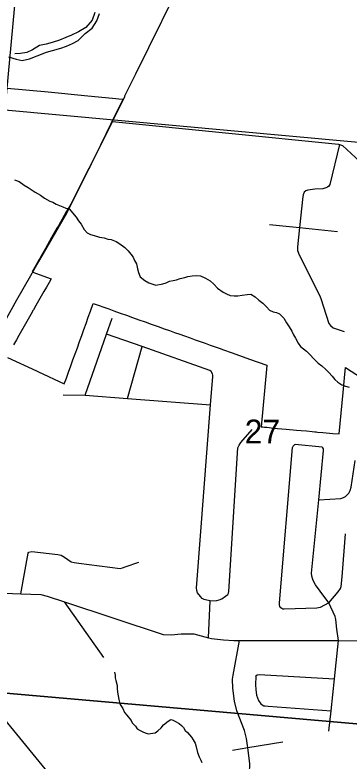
# Model space of a CAD drawing. Extents: x 0 to 34, y -3.9 to 26.2.
# Drawn here: x 4.192 to 4.778, y 19.139 to 20.448 of the extents above; entities that cross this region are included whole.
import ezdxf

# ---------------------------------------------------------------- set-up
doc = ezdxf.new("R2010")
doc.units = 0
for name, color, linetype in [('GM_X_City_Street', 7, 'Continuous'), ('GM_X_Corporation', 7, 'Continuous'), ('GM_X_County_Road', 7, 'Continuous'), ('GM_X_Interchange_Ramps', 7, 'Continuous'), ('GM_X_Minor_River', 7, 'Continuous'), ('GM_X_Section', 7, 'Continuous'), ('GM_X_Section_Text', 7, 'Continuous'), ('GM_X_State_Shield', 7, 'Continuous'), ('GM_X_US_Route', 7, 'Continuous')]:
    doc.layers.add(name, color=color, linetype=linetype)

msp = doc.modelspace()

# ---------------------------------------------------------------- linework, layer by layer
at = {"layer": 'GM_X_City_Street'}
for p, q in [((4.3893, 19.7752), (4.4152, 19.8662)), ((4.3477, 19.3208), (4.2785, 19.4187)), ((4.5311, 19.3555), (4.5342, 19.4203))]:
    msp.add_line(p, q, dxfattribs=at)
for points in [[(4.7613, 20.2207), (4.7441, 20.1505), (4.7422, 20.1479), (4.7398, 20.1461), (4.7371, 20.1448), (4.7318, 20.1432), (4.7177, 20.1423), (4.7056, 20.1406), (4.7019, 20.1392), (4.6994, 20.1369), (4.6976, 20.1327), (4.6966, 20.1294), (4.691, 20.075), (4.6875, 20.0413), (4.6873, 20.0367), (4.6877, 20.0345), (4.6906, 20.0272), (4.7262, 19.9566), (4.7283, 19.9506), (4.7424, 19.9068), (4.7453, 19.903), (4.7502, 19.8991), (4.7695, 19.8926)], [(4.6384, 20.0803), (4.691, 20.075), (4.7578, 20.0681)], [(4.3151, 19.7808), (4.3525, 19.8883), (4.3622, 19.9162)], [(4.5342, 19.4203), (4.5282, 19.4213), (4.524, 19.4224), (4.5204, 19.4245), (4.517, 19.4279), (4.5122, 19.4341), (4.5108, 19.4382), (4.5105, 19.4429), (4.5113, 19.4577), (4.5351, 19.7643), (4.539, 19.8139), (4.5387, 19.8161), (4.5382, 19.8183), (4.536, 19.8224), (4.5338, 19.8244), (4.4152, 19.8662), (4.3525, 19.8883)], [(4.2765, 19.7814), (4.3151, 19.7808), (4.3893, 19.7752), (4.5351, 19.7643)], [(4.5342, 19.4203), (4.546, 19.4207), (4.55, 19.4219), (4.5548, 19.4239), (4.5613, 19.4283), (4.565, 19.4315), (4.5663, 19.4337), (4.5671, 19.4369), (4.5828, 19.6886), (4.5852, 19.6934), (4.5883, 19.6979), (4.6079, 19.7209)], [(4.7421, 19.4167), (4.7273, 19.4087), (4.7212, 19.4073), (4.6643, 19.4054), (4.6615, 19.4057), (4.6581, 19.408), (4.6564, 19.4102), (4.6559, 19.413), (4.6558, 19.4166), (4.6788, 19.689), (4.6791, 19.6901), (4.68, 19.6913)], [(4.7422, 19.1914), (4.7462, 19.2273), (4.7523, 19.2835), (4.7596, 19.3504), (4.7567, 19.3706), (4.7547, 19.3874), (4.7542, 19.3905), (4.7535, 19.3928), (4.7421, 19.4167), (4.7273, 19.4371), (4.7189, 19.4484), (4.7164, 19.4525), (4.7142, 19.4576), (4.7127, 19.4633), (4.7122, 19.469), (4.7246, 19.5975), (4.7329, 19.6838), (4.733, 19.6856), (4.7328, 19.6871), (4.7321, 19.6888), (4.7307, 19.6899), (4.6831, 19.6942), (4.6822, 19.694), (4.6813, 19.6931), (4.68, 19.6913)], [(4.7246, 19.5975), (4.7637, 19.5998), (4.7679, 19.6014), (4.7714, 19.6034), (4.7772, 19.6093), (4.78, 19.6137), (4.7817, 19.6194), (4.7886, 19.6667)], [(4.7421, 19.4167), (4.7588, 19.4363), (4.7628, 19.4419), (4.7643, 19.4456), (4.7659, 19.4623), (4.7716, 19.5377)], [(4.2023, 19.4327), (4.2151, 19.5036), (4.2163, 19.5058), (4.2213, 19.5065), (4.267, 19.5018), (4.2731, 19.5005), (4.2787, 19.497), (4.2906, 19.4887), (4.2955, 19.4874), (4.3038, 19.4864), (4.3764, 19.4769), (4.3806, 19.4783), (4.3852, 19.4801), (4.4089, 19.4882)], [(4.0164, 19.3649), (4.0916, 19.4215), (4.1051, 19.4272), (4.1238, 19.4316), (4.1572, 19.4341), (4.2023, 19.4327), (4.2372, 19.4316), (4.2485, 19.4287), (4.2785, 19.4187), (4.4519, 19.3613), (4.4663, 19.3606), (4.4834, 19.3624), (4.5054, 19.3622), (4.5311, 19.3555), (4.5363, 19.3541), (4.5575, 19.3517), (4.576, 19.3508), (4.5859, 19.3508), (4.6386, 19.3507), (4.6468, 19.3506)], [(4.6468, 19.3506), (4.7596, 19.3504), (4.8734, 19.3501), (4.8869, 19.3459), (4.9022, 19.3379), (4.9554, 19.3106), (4.9652, 19.31), (4.9759, 19.3109), (4.9915, 19.3139), (5.0737, 19.3523), (5.0919, 19.3626), (5.0948, 19.3642), (5.1135, 19.3812), (5.1213, 19.3897), (5.1348, 19.4156), (5.1398, 19.4181), (5.1501, 19.4178), (5.2147, 19.4085), (5.229, 19.4051), (5.3139, 19.3743), (5.3672, 19.3587), (5.3711, 19.3576), (5.4138, 19.3496)], [(4.5821, 18.7164), (4.5856, 18.7909), (4.5853, 18.7951), (4.5799, 18.807), (4.5782, 18.8131), (4.5785, 18.8233), (4.6019, 19.1003), (4.6034, 19.1177), (4.6039, 19.1344), (4.6002, 19.1628), (4.5998, 19.1664), (4.5978, 19.179), (4.5947, 19.1927), (4.5808, 19.2273), (4.5771, 19.2441), (4.5739, 19.2673), (4.5733, 19.2827), (4.5745, 19.2897), (4.5859, 19.3508)], [(4.6146, 19.2883), (4.6135, 19.2727), (4.6141, 19.2647), (4.6157, 19.2548), (4.6171, 19.2502), (4.6192, 19.2452), (4.6229, 19.2398), (4.6254, 19.2377), (4.6281, 19.2363), (4.6305, 19.2359), (4.6357, 19.2357), (4.7462, 19.2273)], [(4.6146, 19.2883), (4.6151, 19.2891), (4.6161, 19.29), (4.6168, 19.2905), (4.6178, 19.2907), (4.62, 19.2908), (4.7523, 19.2835)], [(4.5734, 19.1584), (4.6002, 19.1628), (4.6617, 19.1731)]]:
    msp.add_lwpolyline(points, dxfattribs=at)
at = {"layer": 'GM_X_Corporation'}
for points in [[(4.1782, 20.3198), (4.2502, 20.3128), (4.3136, 20.3067), (4.3688, 20.3013), (4.3739, 20.3009), (4.3815, 20.3001), (4.3632, 20.2632), (4.3603, 20.2568), (4.3418, 20.2195), (4.3411, 20.2181), (4.3393, 20.2144), (4.3295, 20.1947), (4.3291, 20.1938), (4.3271, 20.1896), (4.3256, 20.1865), (4.3246, 20.1845), (4.3237, 20.1826), (4.323, 20.1813), (4.3217, 20.1786), (4.2919, 20.1198), (4.2897, 20.116), (4.2856, 20.1091), (4.2819, 20.1026), (4.268, 20.0781), (4.2655, 20.0737), (4.2561, 20.0573), (4.2453, 20.0383), (4.2365, 20.0228), (4.2354, 20.0209), (4.2334, 20.0174), (4.2319, 20.0147), (4.2265, 20.0053), (4.2218, 19.9971), (4.2281, 19.9948), (4.2553, 19.985), (4.2516, 19.9785), (4.2469, 19.9703), (4.2427, 19.9629), (4.238, 19.9547), (4.2333, 19.9465), (4.2286, 19.9382), (4.2244, 19.9308), (4.2239, 19.93), (4.2197, 19.9226), (4.2127, 19.9102), (4.2033, 19.8938), (4.1986, 19.8856), (4.1944, 19.8782), (4.1892, 19.8691)], [(4.179, 19.8473), (4.2295, 19.8237), (4.2334, 19.8219), (4.2784, 19.8007), (4.2821, 19.8108), (4.2859, 19.8215), (4.2898, 19.8322), (4.2936, 19.8429), (4.2975, 19.8536), (4.3013, 19.8643), (4.3052, 19.875), (4.309, 19.8857), (4.3128, 19.8964), (4.3167, 19.907), (4.3205, 19.9177), (4.3244, 19.9284), (4.3292, 19.9419), (4.3565, 19.9322), (4.3654, 19.929), (4.3764, 19.9251), (4.3873, 19.9212), (4.3983, 19.9173), (4.4092, 19.9134), (4.4201, 19.9095), (4.431, 19.9056), (4.4428, 19.9014), (4.4537, 19.8976), (4.4628, 19.8943), (4.4718, 19.8911), (4.4808, 19.8879), (4.4893, 19.8849), (4.4992, 19.8814), (4.5081, 19.8782), (4.5168, 19.8751), (4.5254, 19.872), (4.5344, 19.8688), (4.5516, 19.8627), (4.5559, 19.8612), (4.5728, 19.8552), (4.603, 19.8444), (4.6336, 19.8335), (4.6336, 19.8331), (4.6236, 19.7257), (4.6264, 19.7252), (4.6297, 19.7249), (4.6335, 19.7246), (4.6376, 19.7242), (4.6414, 19.7239), (4.6525, 19.7228), (4.6673, 19.7215), (4.6859, 19.7198), (4.6936, 19.7191), (4.7035, 19.7182), (4.7129, 19.7173), (4.7176, 19.7168), (4.7199, 19.7165), (4.7223, 19.7163), (4.7223, 19.7163), (4.7223, 19.7164), (4.7317, 19.7156), (4.7494, 19.7139), (4.7607, 19.7129), (4.7675, 19.7855), (4.77, 19.8117), (4.7716, 19.8293), (4.7996, 19.8117)]]:
    msp.add_lwpolyline(points, dxfattribs=at)
at = {"layer": 'GM_X_County_Road'}
for points in [[(4.3628, 20.2608), (4.7594, 20.2214), (4.7613, 20.2207), (4.7666, 20.2189), (4.7965, 20.1906), (4.9395, 20.0396), (4.9451, 20.0349), (4.9572, 20.0286), (5.1535, 19.9477)], [(4.531, 18.7211), (4.5289, 18.7386), (4.5326, 18.7785), (4.5323, 18.7842), (4.5313, 18.7911), (4.5289, 18.798), (4.5251, 18.8049), (4.5234, 18.8071), (4.4853, 18.8456), (4.4237, 18.9101), (4.3697, 18.9768), (4.2658, 19.0997), (4.169, 19.2187), (4.1666, 19.2228), (4.1624, 19.2298), (4.1556, 19.2516), (4.1308, 19.3038), (4.1279, 19.3099), (4.1253, 19.3129), (4.1209, 19.3168), (4.1102, 19.3217), (4.0164, 19.3649), (3.9713, 19.3857), (3.9077, 19.4237)]]:
    msp.add_lwpolyline(points, dxfattribs=at)
at = {"layer": 'GM_X_Interchange_Ramps'}
for points in [[(4.1782, 20.3198), (4.2502, 20.3128), (4.3136, 20.3067), (4.3688, 20.3013), (4.3739, 20.3009), (4.3815, 20.3001), (4.3632, 20.2632), (4.3603, 20.2568), (4.3418, 20.2195), (4.3411, 20.2181), (4.3393, 20.2144), (4.3295, 20.1947), (4.3291, 20.1938), (4.3271, 20.1896), (4.3256, 20.1865), (4.3246, 20.1845), (4.3237, 20.1826), (4.323, 20.1813), (4.3217, 20.1786), (4.2919, 20.1198), (4.2897, 20.116), (4.2856, 20.1091), (4.2819, 20.1026), (4.268, 20.0781), (4.2655, 20.0737), (4.2561, 20.0573), (4.2453, 20.0383), (4.2365, 20.0228), (4.2354, 20.0209), (4.2334, 20.0174), (4.2319, 20.0147), (4.2265, 20.0053), (4.2218, 19.9971), (4.2281, 19.9948), (4.2553, 19.985), (4.2516, 19.9785), (4.2469, 19.9703), (4.2427, 19.9629), (4.238, 19.9547), (4.2333, 19.9465), (4.2286, 19.9382), (4.2244, 19.9308), (4.2239, 19.93), (4.2197, 19.9226), (4.2127, 19.9102), (4.2033, 19.8938), (4.1986, 19.8856), (4.1944, 19.8782), (4.1892, 19.8691)], [(4.179, 19.8473), (4.2295, 19.8237), (4.2334, 19.8219), (4.2784, 19.8007), (4.2821, 19.8108), (4.2859, 19.8215), (4.2898, 19.8322), (4.2936, 19.8429), (4.2975, 19.8536), (4.3013, 19.8643), (4.3052, 19.875), (4.309, 19.8857), (4.3128, 19.8964), (4.3167, 19.907), (4.3205, 19.9177), (4.3244, 19.9284), (4.3292, 19.9419), (4.3565, 19.9322), (4.3654, 19.929), (4.3764, 19.9251), (4.3873, 19.9212), (4.3983, 19.9173), (4.4092, 19.9134), (4.4201, 19.9095), (4.431, 19.9056), (4.4428, 19.9014), (4.4537, 19.8976), (4.4628, 19.8943), (4.4718, 19.8911), (4.4808, 19.8879), (4.4893, 19.8849), (4.4992, 19.8814), (4.5081, 19.8782), (4.5168, 19.8751), (4.5254, 19.872), (4.5344, 19.8688), (4.5516, 19.8627), (4.5559, 19.8612), (4.5728, 19.8552), (4.603, 19.8444), (4.6336, 19.8335), (4.6336, 19.8331), (4.6236, 19.7257), (4.6264, 19.7252), (4.6297, 19.7249), (4.6335, 19.7246), (4.6376, 19.7242), (4.6414, 19.7239), (4.6525, 19.7228), (4.6673, 19.7215), (4.6859, 19.7198), (4.6936, 19.7191), (4.7035, 19.7182), (4.7129, 19.7173), (4.7176, 19.7168), (4.7199, 19.7165), (4.7223, 19.7163), (4.7223, 19.7163), (4.7223, 19.7164), (4.7317, 19.7156), (4.7494, 19.7139), (4.7607, 19.7129), (4.7675, 19.7855), (4.77, 19.8117), (4.7716, 19.8293), (4.7996, 19.8117)]]:
    msp.add_lwpolyline(points, dxfattribs=at)
at = {"layer": 'GM_X_Minor_River'}
for points in [[(4.1805, 20.3744), (4.1937, 20.3704), (4.2043, 20.3679), (4.2176, 20.3707), (4.231, 20.3765), (4.2474, 20.3827), (4.2577, 20.3855), (4.2722, 20.3894), (4.2821, 20.393), (4.2925, 20.3978), (4.3028, 20.4029), (4.3148, 20.4152), (4.3271, 20.4245), (4.3357, 20.4377), (4.3401, 20.4505)], [(4.3322, 20.4522), (4.327, 20.4386), (4.3161, 20.4262), (4.3031, 20.4185), (4.2908, 20.4123), (4.2809, 20.4083), (4.2702, 20.4039), (4.2572, 20.3996), (4.2465, 20.3968), (4.2351, 20.3943), (4.2224, 20.387), (4.2129, 20.3818), (4.2014, 20.3801), (4.1916, 20.3796)], [(4.1908, 20.159), (4.199, 20.1556), (4.2079, 20.1492), (4.2149, 20.1451), (4.222, 20.1406), (4.2275, 20.137), (4.2365, 20.132), (4.2439, 20.1268), (4.2528, 20.1211), (4.2584, 20.1193), (4.264, 20.1161), (4.2756, 20.1114), (4.2808, 20.1089), (4.2876, 20.1075), (4.293, 20.1008), (4.2995, 20.0933), (4.3035, 20.0871), (4.3082, 20.0808), (4.3131, 20.0718), (4.3186, 20.0659), (4.3242, 20.0626), (4.3306, 20.0612), (4.34, 20.0582), (4.3483, 20.0567), (4.355, 20.0549), (4.3607, 20.0539), (4.3693, 20.0505), (4.376, 20.0464), (4.3845, 20.04), (4.3903, 20.034), (4.395, 20.0285), (4.3994, 20.023), (4.4018, 20.0172), (4.405, 20.0114), (4.4065, 20.0026), (4.4086, 19.996), (4.4117, 19.9887), (4.4194, 19.9819), (4.4269, 19.9782), (4.4336, 19.9756), (4.4392, 19.9742), (4.4511, 19.9764), (4.4569, 19.9781), (4.4627, 19.9809), (4.4696, 19.9821), (4.4753, 19.9834), (4.4819, 19.9854), (4.4899, 19.9873), (4.4953, 19.989), (4.5026, 19.9906), (4.5095, 19.9911), (4.5174, 19.9904), (4.526, 19.9862), (4.5345, 19.9813), (4.5404, 19.9757), (4.5473, 19.9686), (4.5569, 19.9614), (4.5629, 19.9588), (4.5692, 19.9559), (4.5764, 19.9552), (4.5829, 19.955), (4.5906, 19.9565), (4.5993, 19.9573), (4.6058, 19.9582), (4.6132, 19.9537), (4.6198, 19.9474), (4.6268, 19.9421), (4.6331, 19.9362), (4.6385, 19.9302), (4.6449, 19.9269), (4.6505, 19.9263), (4.6561, 19.9238), (4.6634, 19.9159), (4.6684, 19.9081), (4.6731, 19.901), (4.6774, 19.8933), (4.6805, 19.887), (4.6841, 19.8812), (4.6887, 19.8723), (4.6926, 19.8664), (4.703, 19.858), (4.7088, 19.8524)], [(4.7088, 19.8524), (4.7161, 19.8445), (4.7238, 19.8374), (4.7301, 19.8322), (4.7367, 19.8266), (4.7422, 19.821), (4.748, 19.8143), (4.7527, 19.8084), (4.7582, 19.8036), (4.7652, 19.7991), (4.7716, 19.797), (4.778, 19.7952)], [(4.3665, 19.2953), (4.3674, 19.2899), (4.3676, 19.2854), (4.3686, 19.2804), (4.3709, 19.2715), (4.371, 19.2662), (4.3719, 19.2601), (4.3741, 19.2471), (4.375, 19.2425), (4.3764, 19.2382), (4.3811, 19.2316), (4.3842, 19.2242), (4.3878, 19.2199), (4.3954, 19.2101), (4.3976, 19.2062), (4.403, 19.2003), (4.4063, 19.1959), (4.4115, 19.1927), (4.4163, 19.1906), (4.4201, 19.1889), (4.4253, 19.1872), (4.4295, 19.1874), (4.4375, 19.1889), (4.4422, 19.1925), (4.4485, 19.1976), (4.4525, 19.2028), (4.4608, 19.2093), (4.4654, 19.2121), (4.4692, 19.2108), (4.4733, 19.2084), (4.48, 19.205), (4.484, 19.2015), (4.4877, 19.1983), (4.4905, 19.1928), (4.4946, 19.1892), (4.5015, 19.1813), (4.5043, 19.1763), (4.5079, 19.1704), (4.5089, 19.1666), (4.5122, 19.1543), (4.5149, 19.1466), (4.5181, 19.1407), (4.5195, 19.1369)]]:
    msp.add_lwpolyline(points, dxfattribs=at)
at = {"layer": 'GM_X_Section'}
for points in [[(4.1738, 20.2814), (5.1778, 20.1897), (5.0852, 19.1785), (4.0751, 19.2669)], [(4.0751, 19.2669), (5.0852, 19.1785), (4.9898, 18.1753), (3.9744, 18.2676)]]:
    msp.add_lwpolyline(points, close=True, dxfattribs=at)
at = {"layer": 'GM_X_State_Shield'}
msp.add_lwpolyline([(5.2454, 20.9), (4.2313, 20.9), (4.1738, 20.2814), (5.1778, 20.1897)], close=True, dxfattribs=at)
at = {"layer": 'GM_X_US_Route'}
msp.add_line((4.2198, 19.9911), (4.2303, 20.0094), dxfattribs=at)
for points in [[(4.3843, 20.3049), (4.3848, 20.3058), (4.4037, 20.3445), (4.4956, 20.531), (4.5144, 20.5725)], [(4.2303, 20.0094), (4.2355, 20.0186), (4.2826, 20.1005), (4.3628, 20.2608), (4.3843, 20.3049)], [(3.741, 19.0851), (3.7702, 19.146), (3.7904, 19.1882), (3.8018, 19.2119), (3.8239, 19.258), (3.8314, 19.2736), (3.8366, 19.2841), (3.8701, 19.3518), (3.9077, 19.4237), (3.9387, 19.484), (3.9742, 19.5493), (4.0332, 19.6577), (4.048, 19.685), (4.1418, 19.8529), (4.1951, 19.9481), (4.2198, 19.9911)]]:
    msp.add_lwpolyline(points, dxfattribs=at)

# ---------------------------------------------------------------- texts
at = {"layer": 'GM_X_Section_Text'}
msp.add_text('27', height=0.04186, rotation=0, dxfattribs=at).set_placement((4.5948, 19.6963))

doc.saveas('drawing.dxf')
